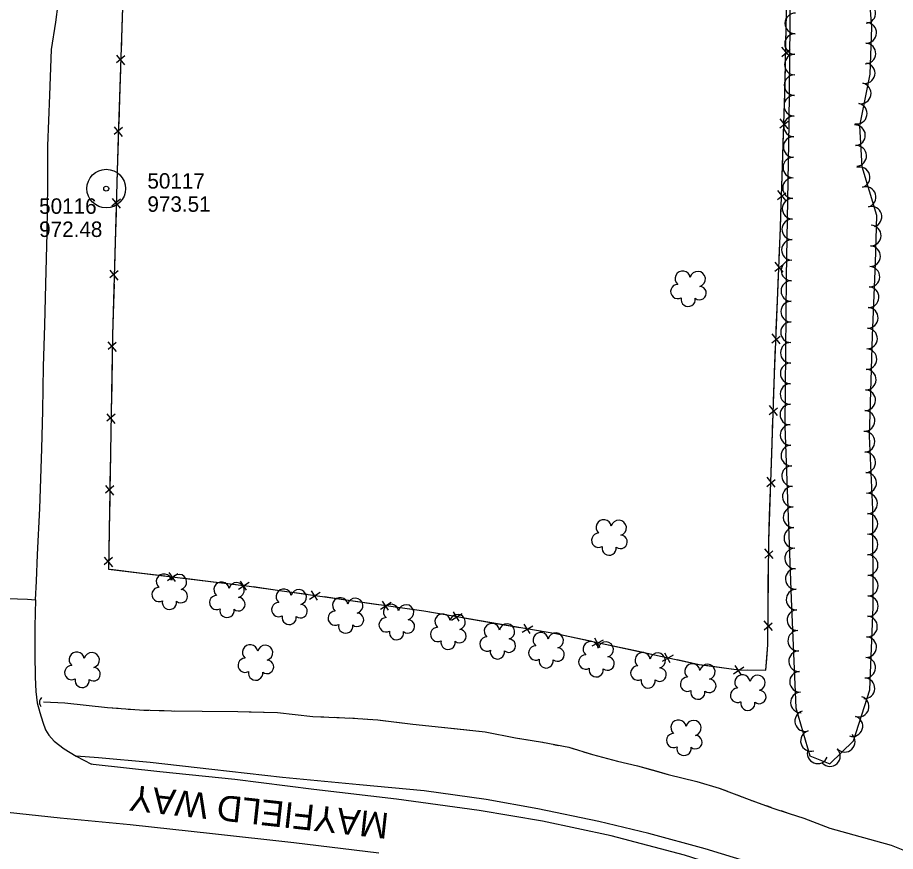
# Model space of a CAD drawing. Extents: x 353423 to 364002, y 127000 to 201942.
# Drawn here: x 359202.5 to 359543.4, y 133674.1 to 133998.1 of the extents above; entities that cross this region are included whole.
import ezdxf

# ---------------------------------------------------------------- set-up
doc = ezdxf.new("R2010")
doc.units = 0
for name, color, linetype in [('E_DTM_SlopeBottom', 7, 'Continuous'), ('E_DTM_SlopeTop', 7, 'Continuous'), ('E_FEN_Generic', 7, 'Continuous'), ('E_RDWY_AsphConc', 7, 'Continuous'), ('E_RW_IP', 7, 'Continuous'), ('E_STRUCT_WingWall', 7, 'Continuous')]:
    doc.layers.add(name, color=color, linetype=linetype)

msp = doc.modelspace()

# ---------------------------------------------------------------- linework, layer by layer
at = {"layer": 'E_DTM_SlopeBottom'}
for p, q in [((359499.22, 133982.99), (359502.44, 133985.73)), ((359502.45, 133982.77), (359499.28, 133986.54)), ((359244.11, 133983.19), (359240.85, 133980.5)), ((359240.88, 133983.47), (359243.99, 133979.65)), ((359498.47, 133955.17), (359501.73, 133957.86)), ((359501.7, 133954.89), (359498.58, 133958.71)), ((359243.2, 133955.35), (359239.94, 133952.65)), ((359239.97, 133955.62), (359243.08, 133951.8)), ((359500.79, 133927.05), (359497.67, 133930.87)), ((359242.38, 133927.5), (359239.13, 133924.8)), ((359239.15, 133927.77), (359242.28, 133923.96)), ((359497.56, 133927.32), (359500.82, 133930.01)), ((359499.74, 133899.19), (359496.66, 133903.04)), ((359241.58, 133899.66), (359238.33, 133896.95)), ((359238.34, 133899.92), (359241.47, 133896.11)), ((359496.52, 133899.49), (359499.8, 133902.16)), ((359495.38, 133871.66), (359498.66, 133874.32)), ((359498.61, 133871.36), (359495.53, 133875.2)), ((359237.57, 133872.05), (359240.74, 133868.28)), ((359240.8, 133871.82), (359237.59, 133869.08)), ((359494.34, 133843.81), (359497.61, 133846.49)), ((359497.58, 133843.53), (359494.47, 133847.35)), ((359237.09, 133844.19), (359240.26, 133840.42)), ((359240.32, 133843.97), (359237.1, 133841.23)), ((359493.38, 133815.96), (359496.65, 133818.65)), ((359496.61, 133815.68), (359493.5, 133819.51)), ((359236.6, 133816.34), (359239.78, 133812.57)), ((359239.84, 133816.11), (359236.62, 133813.37)), ((359492.59, 133788.08), (359495.78, 133790.85)), ((359495.83, 133787.88), (359492.62, 133791.62)), ((359236.12, 133788.48), (359239.3, 133784.71)), ((359239.36, 133788.26), (359236.14, 133785.52)), ((359260.65, 133779.32), (359264.73, 133782.09)), ((359261.21, 133782.52), (359263.61, 133779.04)), ((359288.31, 133775.98), (359292.39, 133778.75)), ((359288.87, 133779.17), (359291.26, 133775.69)), ((359315.87, 133772.15), (359320.01, 133774.83)), ((359316.49, 133775.33), (359318.82, 133771.8)), ((359343.45, 133768.23), (359347.59, 133770.92)), ((359344.08, 133771.42), (359346.4, 133767.89)), ((359371.65, 133767.17), (359373.87, 133763.57)), ((359370.93, 133764), (359375.15, 133766.56)), ((359495.58, 133760.02), (359492.37, 133763.77)), ((359398.39, 133759.27), (359402.6, 133761.83)), ((359399.11, 133762.43), (359401.33, 133758.83)), ((359492.34, 133760.22), (359495.53, 133762.99)), ((359425.66, 133753.95), (359429.97, 133756.34)), ((359426.51, 133757.08), (359428.57, 133753.39)), ((359452.9, 133748.1), (359457.21, 133750.48)), ((359453.74, 133751.23), (359455.81, 133747.54)), ((359481.05, 133746.36), (359483.37, 133742.83)), ((359480.43, 133743.17), (359484.56, 133745.86))]:
    msp.add_line(p, q, dxfattribs=at)
for points in [[(359243.6, 134013.49), (359241.59, 133951.92), (359239.35, 133874.73), (359237.78, 133783.84), (359292.38, 133777.24), (359360.27, 133767.6), (359411.44, 133758.79), (359467.15, 133746.81), (359482.51, 133744.64), (359493.04, 133744.6), (359493.79, 133754.42), (359494.15, 133794.65), (359496.39, 133859.53), (359498.71, 133916.48), (359500.54, 133972.77), (359501.42, 134023.05)], [(359243.35, 134005.84), (359242.98, 133994.52)], [(359500.81, 133988.22), (359501.01, 133999.54)], [(359242.98, 133994.52), (359242.65, 133984.57)], [(359500.5, 133971.68), (359500.54, 133972.77), (359500.69, 133981.64)], [(359242.44, 133977.99), (359242.07, 133966.68)], [(359500.13, 133960.37), (359500.5, 133971.68)], [(359242.07, 133966.68), (359241.74, 133956.72)], [(359499.6, 133943.84), (359499.92, 133953.79)], [(359241.53, 133950.15), (359241.21, 133938.83)], [(359499.23, 133932.52), (359499.6, 133943.84)], [(359241.21, 133938.83), (359240.92, 133928.88)], [(359498.69, 133915.99), (359498.71, 133916.48), (359499.02, 133925.94)], [(359240.73, 133922.3), (359240.4, 133910.98)], [(359498.23, 133904.68), (359498.69, 133915.99)], [(359240.4, 133910.98), (359240.11, 133901.03)], [(359497.55, 133888.15), (359497.96, 133898.1)], [(359239.92, 133894.45), (359239.6, 133883.13)], [(359497.09, 133876.84), (359497.55, 133888.15)], [(359239.6, 133883.13), (359239.35, 133874.73), (359239.33, 133873.18)], [(359496.42, 133860.32), (359496.83, 133870.27)], [(359239.21, 133866.6), (359239.02, 133855.28)], [(359496.02, 133849), (359496.39, 133859.53), (359496.42, 133860.32)], [(359239.02, 133855.28), (359238.85, 133845.32)], [(359495.45, 133832.48), (359495.8, 133842.43)], [(359238.73, 133838.74), (359238.54, 133827.42)], [(359495.06, 133821.16), (359495.45, 133832.48)], [(359238.54, 133827.42), (359238.36, 133817.47)], [(359494.49, 133804.63), (359494.84, 133814.58)], [(359238.25, 133810.89), (359238.05, 133799.57)], [(359494.14, 133793.32), (359494.15, 133794.65), (359494.49, 133804.63)], [(359238.05, 133799.57), (359237.88, 133789.61)], [(359238.59, 133783.74), (359249.83, 133782.39)], [(359493.99, 133776.78), (359494.08, 133786.74)], [(359249.83, 133782.39), (359259.71, 133781.19)], [(359266.24, 133780.4), (359277.48, 133779.04)], [(359277.48, 133779.04), (359287.37, 133777.85)], [(359293.9, 133777.02), (359305.11, 133775.43)], [(359305.11, 133775.43), (359314.97, 133774.03)], [(359493.89, 133765.46), (359493.99, 133776.78)], [(359321.48, 133773.11), (359332.69, 133771.52)], [(359332.69, 133771.52), (359342.55, 133770.12)], [(359349.07, 133769.19), (359360.27, 133767.6), (359360.28, 133767.6)], [(359360.28, 133767.6), (359370.09, 133765.91)], [(359376.57, 133764.8), (359387.73, 133762.87)], [(359387.73, 133762.87), (359397.54, 133761.18)], [(359404.03, 133760.07), (359411.44, 133758.79), (359415.16, 133757.99)], [(359415.16, 133757.99), (359424.89, 133755.9)], [(359493.37, 133748.93), (359493.79, 133754.42), (359493.83, 133758.88)], [(359431.33, 133754.51), (359442.39, 133752.13)], [(359442.39, 133752.13), (359452.13, 133750.04)], [(359458.56, 133748.65), (359467.15, 133746.81), (359469.66, 133746.45)], [(359469.66, 133746.45), (359479.52, 133745.06)], [(359486.07, 133744.62), (359493.04, 133744.6), (359493.37, 133748.93)]]:
    msp.add_lwpolyline(points, dxfattribs=at)
msp.add_ellipse((359212.83, 133732.11), major_axis=(0.05, 2.18), ratio=0.844111, start_param=0.643667, end_param=2.497898, dxfattribs=at)
at = {"layer": 'E_DTM_SlopeTop'}
for points in [[(359209.48, 133771.9), (359209.83, 133779.06), (359210.19, 133789.49), (359211.07, 133807.29), (359211.91, 133830.47), (359212.29, 133845.4), (359212.52, 133862.5), (359213.06, 133878.52), (359213.5, 133894.53), (359213.95, 133914.46), (359214.18, 133933.14), (359214.23, 133948.28), (359215.06, 133967.88), (359215.62, 133985.69), (359217.28, 133996.27), (359218.23, 134003.21), (359218.66, 134017.55), (359219.05, 134035.74), (359219.45, 134055.23), (359219.61, 134069.78), (359219.6, 134070.64)], [(359198.57, 133772.37), (359206.28, 133772.07), (359209.48, 133771.9), (359209.22, 133761.47), (359209.13, 133750.72), (359209.26, 133741.87), (359209.51, 133736.22), (359210.1, 133731.88), (359211.11, 133728.13), (359212.24, 133724.38), (359213.32, 133721.39), (359214.66, 133719.27), (359216.72, 133717.03), (359220.56, 133713.98), (359225.17, 133711.19), (359231.17, 133708.02)], [(359486.83, 133669.86), (359469.48, 133675.19), (359447.62, 133681.13), (359428.25, 133685.71), (359404.49, 133690.74), (359384.41, 133694.28), (359360.37, 133697.68), (359335.24, 133700.05), (359305.39, 133702.82), (359277.87, 133705.96), (359253.94, 133708.7), (359233.85, 133710.46), (359225.17, 133711.19)], [(359740.04, 133519.85), (359727.91, 133530.59), (359716.11, 133540.08), (359700.03, 133552.62), (359684.87, 133563.97), (359667.21, 133576.85), (359650.53, 133587.71), (359632.43, 133598.91), (359613.09, 133609.51), (359595.75, 133618.69), (359575.21, 133629.57), (359549.46, 133640.85), (359523.6, 133651.47), (359495.08, 133661.94), (359461.51, 133672.71), (359432.97, 133680.19), (359406.28, 133685.93), (359381.7, 133690.04), (359349.57, 133694.44), (359317.55, 133698.25), (359286.84, 133702.05), (359257.69, 133705.09), (359231.86, 133707.95), (359231.17, 133708.02)], [(359342.8, 133673.5), (359309.69, 133677.53), (359278.16, 133681.01), (359246.14, 133684.49), (359218.95, 133687.08), (359186.33, 133690.51)]]:
    msp.add_lwpolyline(points, dxfattribs=at)
at = {"layer": 'E_FEN_Generic'}
msp.add_lwpolyline([(359502.53, 134008.1), (359501.93, 133956.9), (359500.88, 133897.35), (359500.42, 133839.38), (359502.86, 133772.3), (359504.63, 133729.94), (359510.08, 133711.21), (359517.83, 133708.17), (359527.05, 133717.08), (359533.39, 133736.94), (359534.76, 133769.09), (359534.56, 133806.93), (359533.32, 133835.42), (359534.46, 133874.42), (359535.57, 133902.82), (359536.13, 133921.11), (359530.44, 133940.09), (359529.58, 133955.97), (359533.49, 133976.08), (359534.22, 133994.38), (359532.39, 134017.6)], dxfattribs=at)
for centre, radius, start, end in [((359531.69, 133999.85), 4, 274.5328, 94.5174), ((359504.48, 133995.79), 4, 89.3359, 269.3206), ((359532.04, 133992.12), 4, 267.7112, 87.6958), ((359504.39, 133987.79), 4, 89.3359, 269.3206), ((359531.72, 133984.13), 4, 267.7112, 87.6958), ((359504.29, 133979.79), 4, 89.3359, 269.3206), ((359531.43, 133976.46), 4, 258.9971, 78.9818), ((359504.2, 133971.8), 4, 89.3359, 269.3206), ((359529.9, 133968.6), 4, 258.9971, 78.9818), ((359504.1, 133963.8), 4, 89.3359, 269.3206), ((359528.37, 133960.75), 4, 258.9971, 78.9818), ((359504, 133955.79), 4, 88.9997, 268.9844), ((359527.68, 133952.33), 4, 273.1167, 93.1013), ((359503.86, 133947.79), 4, 88.9997, 268.9844), ((359528.11, 133944.34), 4, 273.1167, 93.1013), ((359503.72, 133939.79), 4, 88.9997, 268.9844), ((359529.48, 133936.01), 4, 286.7107, 106.6953), ((359503.58, 133931.79), 4, 88.9997, 268.9844), ((359531.78, 133928.35), 4, 286.7107, 106.6953), ((359503.44, 133923.8), 4, 88.9997, 268.9844), ((359534.07, 133920.69), 4, 286.7107, 106.6953), ((359503.3, 133915.8), 4, 88.9997, 268.9844), ((359533.8, 133913.37), 4, 268.2339, 88.2186), ((359503.16, 133907.8), 4, 88.9997, 268.9844), ((359533.55, 133905.37), 4, 268.2339, 88.2186), ((359503.02, 133899.8), 4, 88.9997, 268.9844), ((359460.76, 133896.67), 2.97, 7.7946, 229.0284), ((359533.26, 133897.4), 4, 267.7819, 87.7665), ((359466.61, 133896.5), 2.97, 285.4454, 168.4187), ((359458.85, 133891.65), 2.78, 90.7655, 298.5384), ((359467.32, 133891.02), 2.61, 230.1506, 88.0832), ((359502.93, 133891.82), 4, 89.5556, 269.5402), ((359532.95, 133889.4), 4, 267.7819, 87.7665), ((359462.89, 133888.61), 2.78, 167.4425, 8.4535), ((359502.87, 133883.83), 4, 89.5556, 269.5402), ((359532.64, 133881.41), 4, 267.7819, 87.7665), ((359502.81, 133875.83), 4, 89.5556, 269.5402), ((359532.34, 133873.4), 4, 268.3313, 88.316), ((359502.74, 133867.83), 4, 89.5556, 269.5402), ((359532.11, 133865.4), 4, 268.3313, 88.316), ((359502.68, 133859.83), 4, 89.5556, 269.5402), ((359531.87, 133857.41), 4, 268.3313, 88.316), ((359502.62, 133851.83), 4, 89.5556, 269.5402), ((359531.64, 133849.41), 4, 268.3313, 88.316), ((359502.55, 133843.83), 4, 89.5556, 269.5402), ((359531.4, 133841.41), 4, 268.3313, 88.316), ((359502.65, 133835.93), 4, 92.0853, 272.07), ((359531.32, 133833.27), 4, 272.4896, 92.4743), ((359502.94, 133827.93), 4, 92.0853, 272.07), ((359531.67, 133825.28), 4, 272.4896, 92.4743), ((359503.23, 133819.94), 4, 92.0853, 272.07), ((359532.01, 133817.28), 4, 272.4896, 92.4743), ((359503.52, 133811.95), 4, 92.0853, 272.07), ((359532.36, 133809.29), 4, 272.4896, 92.4743), ((359503.81, 133803.95), 4, 92.0853, 272.07), ((359532.49, 133801.38), 4, 270.3091, 90.2938), ((359430.07, 133800.03), 2.97, 7.7946, 229.0284), ((359435.92, 133799.85), 2.97, 285.4454, 168.4187), ((359428.15, 133795.01), 2.78, 90.7655, 298.5384), ((359504.1, 133795.96), 4, 92.0853, 272.07), ((359532.53, 133793.38), 4, 270.3091, 90.2938), ((359436.62, 133794.38), 2.61, 230.1506, 88.0832), ((359432.2, 133791.96), 2.78, 167.4425, 8.4535), ((359504.39, 133787.97), 4, 92.0853, 272.07), ((359532.58, 133785.38), 4, 270.3091, 90.2938), ((359504.68, 133779.97), 4, 92.0853, 272.07), ((359259.31, 133778.97), 2.97, 7.7946, 229.0284), ((359265.16, 133778.79), 2.97, 285.4454, 168.4187), ((359532.62, 133777.38), 4, 270.3091, 90.2938), ((359281.67, 133775.85), 2.97, 7.7946, 229.0284), ((359287.52, 133775.67), 2.97, 285.4454, 168.4187), ((359257.4, 133773.95), 2.78, 90.7655, 298.5384), ((359265.87, 133773.31), 2.61, 230.1506, 88.0832), ((359279.76, 133770.82), 2.78, 90.7655, 298.5384), ((359305.82, 133773.1), 2.97, 7.7946, 229.0284), ((359311.67, 133772.92), 2.97, 285.4454, 168.4187), ((359504.97, 133771.99), 4, 92.4007, 272.3853), ((359261.44, 133770.9), 2.78, 167.4425, 8.4535), ((359288.23, 133770.19), 2.61, 230.1506, 88.0832), ((359303.91, 133768.08), 2.78, 90.7655, 298.5384), ((359312.38, 133767.45), 2.61, 230.1506, 88.0832), ((359327.75, 133769.76), 2.97, 7.7946, 229.0284), ((359333.6, 133769.59), 2.97, 285.4454, 168.4187), ((359347.5, 133767.2), 2.97, 7.7946, 229.0284), ((359353.35, 133767.02), 2.97, 285.4454, 168.4187), ((359532.66, 133769.38), 4, 270.3091, 90.2938), ((359283.8, 133767.78), 2.78, 167.4425, 8.4535), ((359325.83, 133764.74), 2.78, 90.7655, 298.5384), ((359334.3, 133764.11), 2.61, 230.1506, 88.0832), ((359505.3, 133764), 4, 92.4007, 272.3853), ((359307.95, 133765.03), 2.78, 167.4425, 8.4535), ((359345.59, 133762.17), 2.78, 90.7655, 298.5384), ((359354.06, 133761.54), 2.61, 230.1506, 88.0832), ((359367.52, 133763.43), 2.97, 7.7946, 229.0284), ((359373.37, 133763.26), 2.97, 285.4454, 168.4187), ((359532.34, 133761.49), 4, 267.5721, 87.5567), ((359329.88, 133761.7), 2.78, 167.4425, 8.4535), ((359365.61, 133758.41), 2.78, 90.7655, 298.5384), ((359374.08, 133757.78), 2.61, 230.1506, 88.0832), ((359386.67, 133759.73), 2.97, 7.7946, 229.0284), ((359392.53, 133759.55), 2.97, 285.4454, 168.4187), ((359505.63, 133756.01), 4, 92.4007, 272.3853), ((359349.63, 133759.13), 2.78, 167.4425, 8.4535), ((359384.76, 133754.7), 2.78, 90.7655, 298.5384), ((359393.23, 133754.07), 2.61, 230.1506, 88.0832), ((359405.61, 133756.24), 2.97, 7.7946, 229.0284), ((359411.46, 133756.06), 2.97, 285.4454, 168.4187), ((359532, 133753.5), 4, 267.5721, 87.5567), ((359292.77, 133751.48), 2.97, 7.7946, 229.0284), ((359298.62, 133751.31), 2.97, 285.4454, 168.4187), ((359369.65, 133755.37), 2.78, 167.4425, 8.4535), ((359403.7, 133751.22), 2.78, 90.7655, 298.5384), ((359412.17, 133750.59), 2.61, 230.1506, 88.0832), ((359425.04, 133752.75), 2.97, 7.7946, 229.0284), ((359430.89, 133752.57), 2.97, 285.4454, 168.4187), ((359225.43, 133748.63), 2.97, 7.7946, 229.0284), ((359231.28, 133748.45), 2.97, 285.4454, 168.4187), ((359388.8, 133751.66), 2.78, 167.4425, 8.4535), ((359423.12, 133747.73), 2.78, 90.7655, 298.5384), ((359431.59, 133747.1), 2.61, 230.1506, 88.0832), ((359445.22, 133748.44), 2.97, 7.7946, 229.0284), ((359451.07, 133748.27), 2.97, 285.4454, 168.4187), ((359505.97, 133748.01), 4, 92.4007, 272.3853), ((359223.52, 133743.61), 2.78, 90.7655, 298.5384), ((359290.86, 133746.46), 2.78, 90.7655, 298.5384), ((359299.33, 133745.83), 2.61, 230.1506, 88.0832), ((359407.74, 133748.17), 2.78, 167.4425, 8.4535), ((359443.31, 133743.42), 2.78, 90.7655, 298.5384), ((359464.53, 133744.08), 2.97, 7.7946, 229.0284), ((359470.38, 133743.91), 2.97, 285.4454, 168.4187), ((359531.66, 133745.51), 4, 267.5721, 87.5567), ((359231.99, 133742.98), 2.61, 230.1506, 88.0832), ((359294.9, 133743.42), 2.78, 167.4425, 8.4535), ((359427.17, 133744.68), 2.78, 167.4425, 8.4535), ((359451.77, 133742.79), 2.61, 230.1506, 88.0832), ((359483.95, 133739.78), 2.97, 7.7946, 229.0284), ((359506.3, 133740.02), 4, 92.4007, 272.3853), ((359227.56, 133740.56), 2.78, 167.4425, 8.4535), ((359447.35, 133740.38), 2.78, 167.4425, 8.4535), ((359462.62, 133739.06), 2.78, 90.7655, 298.5384), ((359471.09, 133738.43), 2.61, 230.1506, 88.0832), ((359489.81, 133739.6), 2.97, 285.4454, 168.4187), ((359531.32, 133737.51), 4, 267.5721, 87.5567), ((359466.66, 133736.02), 2.78, 167.4425, 8.4535), ((359482.04, 133734.76), 2.78, 90.7655, 298.5384), ((359490.51, 133734.13), 2.61, 230.1506, 88.0832), ((359506.64, 133732.03), 4, 92.4007, 272.3853), ((359529.11, 133730.42), 4, 252.3122, 72.2969), ((359486.08, 133731.71), 2.78, 167.4425, 8.4535), ((359508.31, 133724.77), 4, 106.2205, 286.2051), ((359526.68, 133722.8), 4, 252.3122, 72.2969), ((359459.13, 133722.25), 2.97, 7.7946, 229.0284), ((359464.98, 133722.08), 2.97, 285.4454, 168.4187), ((359457.22, 133717.23), 2.78, 90.7655, 298.5384), ((359465.69, 133716.6), 2.61, 230.1506, 88.0832), ((359510.55, 133717.09), 4, 106.2205, 286.2051), ((359523.68, 133716.73), 4, 224.0112, 43.9959), ((359461.26, 133714.18), 2.78, 167.4425, 8.4535), ((359513.15, 133712.25), 4, 158.642, 338.6266), ((359517.93, 133711.18), 4, 224.0112, 43.9959)]:
    msp.add_arc(centre, radius, start, end, dxfattribs=at)
at = {"layer": 'E_RDWY_AsphConc'}
for radius in [7.5, 0.96]:
    msp.add_circle((359236.89, 133931.61), radius, dxfattribs=at)
at = {"layer": 'E_STRUCT_WingWall'}
for points in [[(359212.6, 133732.31), (359220.85, 133731.9), (359237.41, 133730.1), (359249.84, 133729.08), (359262.27, 133728.77), (359274.21, 133728.67), (359288.06, 133728.46), (359303.37, 133728.08), (359317.15, 133726.61), (359332.63, 133725.96), (359342.4, 133725.22), (359355.91, 133723.6), (359367.09, 133722.36), (359384.02, 133720.62), (359395.8, 133718.24), (359406.27, 133716.52), (359416.53, 133714.59), (359425.74, 133711.84), (359435.4, 133709.25), (359443.21, 133707.33), (359455.15, 133704.08), (359466.27, 133701.27), (359474.94, 133698.74), (359487.63, 133693.86), (359495.77, 133691.01), (359502.11, 133688.93), (359507.8, 133687.01), (359517.84, 133683.22), (359527.27, 133680.64), (359541.7, 133676.62), (359549.51, 133673.5)], [(359212.6, 133732.31), (359220.85, 133731.9), (359237.41, 133730.1), (359241.48, 133729.77)], [(359245.47, 133729.44), (359247.46, 133729.28)], [(359251.45, 133729.04), (359253.45, 133728.99)], [(359257.45, 133728.89), (359259.45, 133728.84)], [(359263.45, 133728.76), (359274.21, 133728.67), (359288.06, 133728.46), (359292.45, 133728.35)], [(359292.45, 133728.35), (359303.37, 133728.08), (359317.15, 133726.61), (359321.36, 133726.44)], [(359325.36, 133726.27), (359327.36, 133726.18)], [(359331.35, 133726.02), (359332.63, 133725.96), (359333.35, 133725.91)], [(359337.34, 133725.61), (359339.33, 133725.45)], [(359343.32, 133725.11), (359355.91, 133723.6), (359367.09, 133722.36), (359372.13, 133721.85)], [(359372.13, 133721.85), (359384.02, 133720.62), (359395.8, 133718.24), (359400.77, 133717.43)], [(359404.71, 133716.78), (359406.27, 133716.52), (359406.68, 133716.45)], [(359410.61, 133715.7), (359412.58, 133715.33)], [(359416.51, 133714.59), (359416.53, 133714.59), (359418.43, 133714.02)], [(359422.26, 133712.88), (359425.74, 133711.84), (359435.4, 133709.25), (359443.21, 133707.33), (359450.28, 133705.4)], [(359450.28, 133705.4), (359455.15, 133704.08), (359466.27, 133701.27), (359474.94, 133698.74), (359478.16, 133697.51)], [(359481.89, 133696.07), (359483.76, 133695.35)], [(359487.49, 133693.92), (359487.63, 133693.86), (359489.38, 133693.25)], [(359493.16, 133691.93), (359495.04, 133691.27)], [(359498.84, 133690), (359502.11, 133688.93), (359507.8, 133687.01), (359517.84, 133683.22), (359526.35, 133680.89)], [(359526.35, 133680.89), (359527.27, 133680.64), (359541.7, 133676.62), (359549.51, 133673.5), (359553.91, 133671.99)]]:
    msp.add_lwpolyline(points, dxfattribs=at)

# ---------------------------------------------------------------- texts
at = {"layer": 'E_RDWY_AsphConc'}
for s, p in [('50117', (359252.89, 133931.61)), ('50116', (359210.85, 133921.83)), ('973.51', (359252.89, 133922.61)), ('972.48', (359210.85, 133912.83))]:
    msp.add_text(s, height=6, dxfattribs=at).set_placement(p)
at = {"layer": 'E_RW_IP'}
msp.add_text('MAYFIELD WAY', height=10, rotation=173.7044, dxfattribs=at).set_placement((359347.01, 133688.93))

doc.saveas('drawing.dxf')
